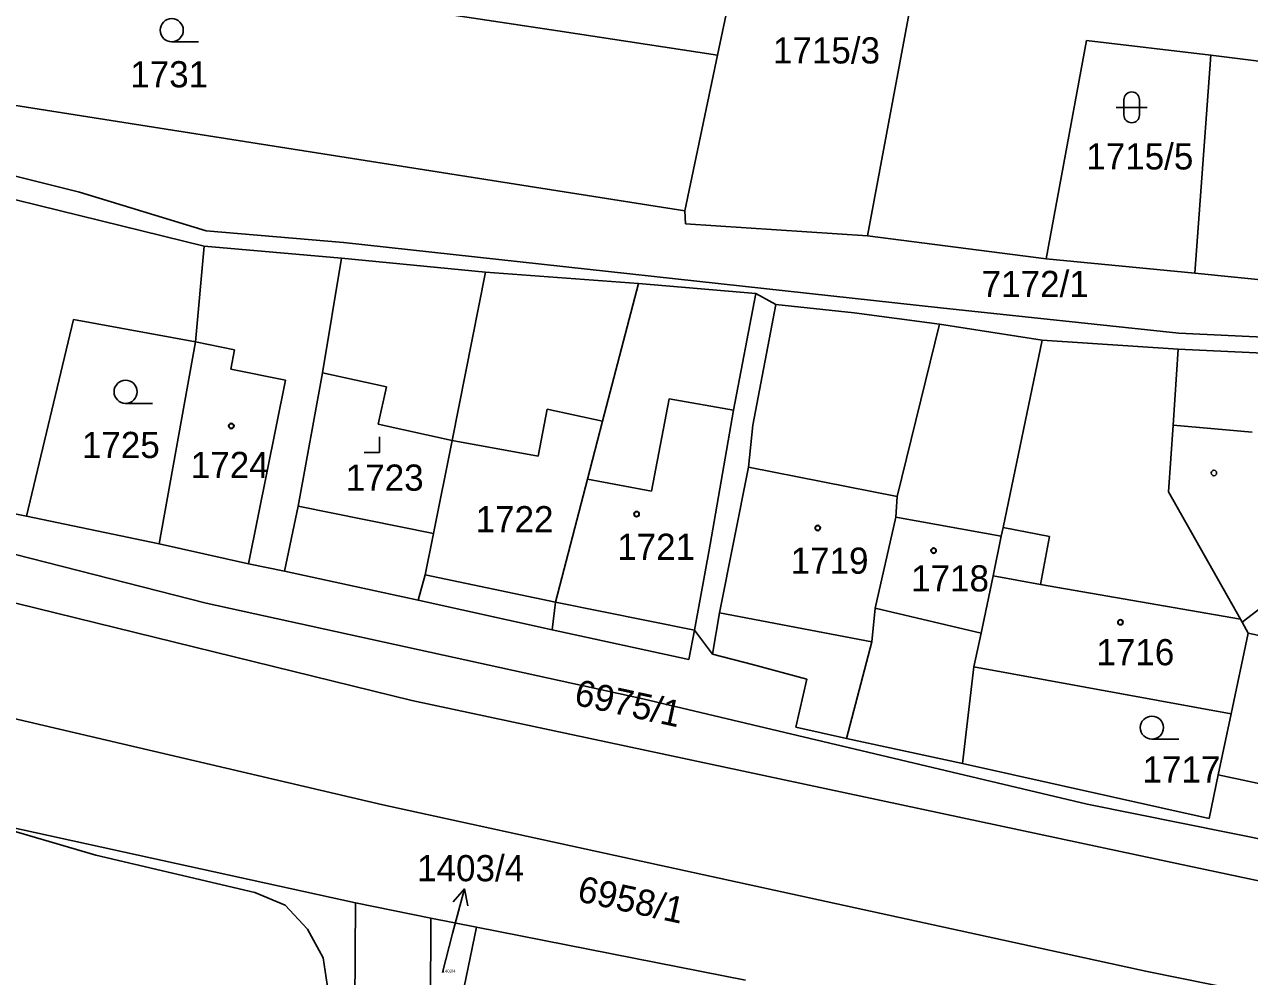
# Model space of a CAD drawing. Extents: x -593183 to -588034, y -1130415 to -1124994.
# Drawn here: x -590080.2 to -590000.6, y -1129409.1 to -1129347.3 of the extents above; entities that cross this region are included whole.
import ezdxf

# ---------------------------------------------------------------- set-up
doc = ezdxf.new("R2010")
doc.units = 0
for name, color, linetype in [('Vrstva 1', 7, 'Continuous'), ('Vrstva 16', 7, 'Continuous'), ('Vrstva 18', 7, 'Continuous'), ('Vrstva 19', 7, 'Continuous'), ('Vrstva 25', 7, 'Continuous'), ('Vrstva 27', 7, 'Continuous'), ('Vrstva 4', 7, 'Continuous')]:
    doc.layers.add(name, color=color, linetype=linetype)

msp = doc.modelspace()

# ---------------------------------------------------------------- linework, layer by layer
at = {"layer": 'Vrstva 1'}
for p, q in [((-590031.96, -1129333.97), (-590035.17, -1129349.33)), ((-590020.91, -1129336.92), (-590025.43, -1129361.05)), ((-590061.71, -1129345.31), (-590045.53, -1129347.76)), ((-590045.53, -1129347.76), (-590035.17, -1129349.33)), ((-590013.83, -1129362.55), (-590011.22, -1129348.37)), ((-590011.22, -1129348.37), (-590003.15, -1129349.34)), ((-590035.17, -1129349.33), (-590037.28, -1129359.43)), ((-590003.15, -1129349.34), (-590004.19, -1129363.49)), ((-590003.15, -1129349.34), (-589985.14, -1129351.52)), ((-590037.28, -1129359.43), (-590088.17, -1129351.42)), ((-590076.58, -1129358.22), (-590088.73, -1129355.19)), ((-590068.5, -1129361.72), (-590085.47, -1129357.56)), ((-590068.36, -1129360.73), (-590076.58, -1129358.22)), ((-590037.24, -1129360.27), (-590037.28, -1129359.43)), ((-590059.44, -1129361.5), (-590068.36, -1129360.73)), ((-590025.43, -1129361.05), (-590037.24, -1129360.27)), ((-590025.43, -1129361.05), (-590013.83, -1129362.55)), ((-590068.5, -1129361.72), (-590069.05, -1129367.94)), ((-590059.58, -1129362.5), (-590068.5, -1129361.72)), ((-590020.69, -1129365.72), (-590059.44, -1129361.5)), ((-590059.58, -1129362.5), (-590060.8, -1129369.94)), ((-590059.58, -1129362.5), (-590050.22, -1129363.41)), ((-590004.19, -1129363.49), (-590013.83, -1129362.55)), ((-590050.22, -1129363.41), (-590052.4, -1129374.34)), ((-590040.3, -1129364.15), (-590050.22, -1129363.41)), ((-590040.3, -1129364.15), (-590042.63, -1129373.08)), ((-590032.69, -1129364.81), (-590040.3, -1129364.15)), ((-589984.38, -1129365.43), (-590004.19, -1129363.49)), ((-590034.14, -1129372.37), (-590032.69, -1129364.81)), ((-590031.38, -1129365.51), (-590032.69, -1129364.81)), ((-590031.38, -1129365.51), (-590032.88, -1129373.34)), ((-590026.3, -1129366.06), (-590031.38, -1129365.51)), ((-590005.21, -1129367.38), (-590020.69, -1129365.72)), ((-590076.98, -1129366.49), (-590080.02, -1129379.26)), ((-590069.05, -1129367.94), (-590076.98, -1129366.49)), ((-590020.76, -1129366.78), (-590026.3, -1129366.06)), ((-590023.51, -1129377.98), (-590020.76, -1129366.78)), ((-590014.1, -1129367.82), (-590020.76, -1129366.78)), ((-589984.93, -1129368.31), (-590005.21, -1129367.38)), ((-590069.05, -1129367.94), (-590071.41, -1129381.05)), ((-590014.1, -1129367.82), (-590016.63, -1129379.99)), ((-590014.1, -1129367.82), (-590005.26, -1129368.41)), ((-590005.59, -1129373.34), (-590005.26, -1129368.41)), ((-589984.99, -1129369.38), (-590005.26, -1129368.41)), ((-590060.8, -1129369.94), (-590062.4, -1129378.61)), ((-590035.65, -1129381.09), (-590034.14, -1129372.37)), ((-590042.63, -1129373.08), (-590043.61, -1129376.86)), ((-590032.88, -1129373.34), (-590033.16, -1129376.07)), ((-590005.88, -1129377.68), (-590005.59, -1129373.34)), ((-590052.4, -1129374.34), (-590053.6, -1129380.37)), ((-590033.16, -1129376.07), (-590035.03, -1129385.52)), ((-590043.61, -1129376.86), (-590045.69, -1129384.83)), ((-590001.22, -1129385.94), (-590005.88, -1129377.68)), ((-590083.99, -1129378.43), (-590080.02, -1129379.26)), ((-590023.6, -1129379.31), (-590023.51, -1129377.98)), ((-590071.41, -1129381.05), (-590080.02, -1129379.26)), ((-590062.4, -1129378.61), (-590063.28, -1129382.83)), ((-590024.94, -1129385.22), (-590023.6, -1129379.31)), ((-590016.63, -1129379.99), (-590016.75, -1129380.55)), ((-590053.6, -1129380.37), (-590054.14, -1129383.07)), ((-590016.75, -1129380.55), (-590017.28, -1129383.12)), ((-590065.62, -1129382.35), (-590071.41, -1129381.05)), ((-590036.66, -1129386.66), (-590035.65, -1129381.09)), ((-590063.28, -1129382.83), (-590065.62, -1129382.35)), ((-590063.28, -1129382.83), (-590054.59, -1129384.7)), ((-590054.14, -1129383.07), (-590054.59, -1129384.7)), ((-590017.28, -1129383.12), (-590018.06, -1129386.85)), ((-590082.19, -1129384.53), (-590055.01, -1129391.21)), ((-590054.59, -1129384.7), (-590045.91, -1129386.62)), ((-590045.69, -1129384.83), (-590045.91, -1129386.62)), ((-590035.03, -1129385.52), (-590035.49, -1129388.2)), ((-590025.14, -1129387.41), (-590024.94, -1129385.22)), ((-590001.1, -1129386.14), (-590001.22, -1129385.94)), ((-590000.71, -1129386.84), (-590001.1, -1129386.14)), ((-590045.91, -1129386.62), (-590037.02, -1129388.56)), ((-590037.02, -1129388.56), (-590036.66, -1129386.66)), ((-590018.06, -1129386.85), (-590018.52, -1129389.04)), ((-590001.83, -1129392.09), (-590000.71, -1129386.84)), ((-590026.79, -1129393.69), (-590025.14, -1129387.41)), ((-590035.49, -1129388.2), (-590032.89, -1129388.87)), ((-590032.89, -1129388.87), (-590029.37, -1129389.83)), ((-590018.52, -1129389.04), (-590019.27, -1129395.3)), ((-590001.83, -1129392.09), (-590018.52, -1129389.04)), ((-590029.37, -1129389.83), (-590030.09, -1129392.94)), ((-590055.01, -1129391.21), (-590005.34, -1129401.8)), ((-590056.9, -1129397.99), (-590084.16, -1129391.61)), ((-590001.83, -1129392.09), (-590002.67, -1129396.05)), ((-590030.09, -1129392.94), (-590026.79, -1129393.69)), ((-590026.79, -1129393.69), (-590019.27, -1129395.3)), ((-590019.27, -1129395.3), (-590003.25, -1129398.87)), ((-590003.25, -1129398.87), (-590002.67, -1129396.05)), ((-590002.67, -1129396.05), (-589989.87, -1129398.75)), ((-590007.28, -1129408.8), (-590056.9, -1129397.99)), ((-590083.72, -1129398.85), (-590075.53, -1129401.25)), ((-590083.72, -1129398.85), (-590058.67, -1129404.34)), ((-590075.53, -1129401.25), (-590065.21, -1129403.68)), ((-590005.34, -1129401.8), (-589982.54, -1129406.63)), ((-590065.21, -1129403.68), (-590063.24, -1129404.51)), ((-590063.24, -1129404.51), (-590061.79, -1129406.07)), ((-590058.67, -1129404.34), (-590058.86, -1129434.44)), ((-590053.86, -1129420.04), (-590053.77, -1129405.34)), ((-590053.77, -1129405.34), (-590050.81, -1129405.93)), ((-590061.79, -1129406.07), (-590060.76, -1129407.93)), ((-590050.81, -1129405.93), (-590033.34, -1129409.38)), ((-590060.76, -1129407.93), (-590060.45, -1129410.08)), ((-589983.97, -1129413.54), (-590007.28, -1129408.8))]:
    msp.add_line(p, q, dxfattribs=at)
msp.add_lwpolyline([(-590035.82, -1129421.91), (-590053.36, -1129418.29), (-590050.81, -1129405.93)], dxfattribs=at)
at = {"layer": 'Vrstva 16'}
msp.add_line((-590053.02, -1129408.88), (-590052.36, -1129406.35), dxfattribs=at)
at = {"layer": 'Vrstva 25'}
for p, q in [((-590068.85, -1129348.46), (-590070.6, -1129348.46)), ((-590008.78, -1129353.22), (-590008.78, -1129352.22)), ((-590007.78, -1129352.22), (-590007.78, -1129353.22)), ((-590009.28, -1129352.72), (-590007.28, -1129352.72)), ((-590071.84, -1129371.93), (-590073.59, -1129371.93)), ((-590057.1, -1129375.11), (-590057.1, -1129374.11)), ((-590057.1, -1129375.11), (-590058.1, -1129375.11)), ((-590005.22, -1129393.73), (-590006.97, -1129393.73)), ((-590052.36, -1129406.35), (-590051.598, -1129403.448))]:
    msp.add_line(p, q, dxfattribs=at)
msp.add_lwpolyline([(-590052.336, -1129404.289), (-590051.598, -1129403.448), (-590051.368, -1129404.543)], dxfattribs=at)
for centre, radius in [((-590070.6, -1129347.71), 0.75), ((-590073.59, -1129371.18), 0.75), ((-590066.73, -1129373.4), 0.175), ((-590066.73, -1129373.4), 0.15), ((-590002.94, -1129376.45), 0.175), ((-590040.42, -1129379.12), 0.175), ((-590040.42, -1129379.12), 0.15), ((-590028.66, -1129380.02), 0.175), ((-590028.66, -1129380.02), 0.15), ((-590021.14, -1129381.49), 0.175), ((-590021.14, -1129381.49), 0.15), ((-590009.01, -1129386.14), 0.175), ((-590009.01, -1129386.14), 0.15), ((-590006.97, -1129392.98), 0.75)]:
    msp.add_circle(centre, radius, dxfattribs=at)
for centre, start, end in [((-590008.28, -1129352.22), 90, 180), ((-590008.28, -1129352.22), 0, 90), ((-590008.28, -1129353.22), 180, 270), ((-590008.28, -1129353.22), 270, 0)]:
    msp.add_arc(centre, 0.5, start, end, dxfattribs=at)
at = {"layer": 'Vrstva 27'}
for p, q in [((-590081.86, -1129381.46), (-590068.36, -1129384.9)), ((-590055.01, -1129391.21), (-590082.19, -1129384.53)), ((-590068.36, -1129384.9), (-590040.01, -1129391.1)), ((-590005.34, -1129401.8), (-590055.01, -1129391.21)), ((-590040.01, -1129391.1), (-590011.16, -1129397.94)), ((-590011.16, -1129397.94), (-589991.31, -1129401.96)), ((-589982.54, -1129406.63), (-590005.34, -1129401.8))]:
    msp.add_line(p, q, dxfattribs=at)
at = {"layer": 'Vrstva 4'}
for p, q in [((-590066.52, -1129368.45), (-590069.05, -1129367.94)), ((-590066.77, -1129369.71), (-590066.52, -1129368.45)), ((-590063.21, -1129370.43), (-590066.77, -1129369.71)), ((-590065.62, -1129382.35), (-590063.21, -1129370.43)), ((-590060.8, -1129369.94), (-590056.65, -1129370.86)), ((-590056.65, -1129370.86), (-590057.19, -1129373.28)), ((-590038.31, -1129371.64), (-590039.45, -1129377.62)), ((-590038.31, -1129371.64), (-590034.14, -1129372.37)), ((-590046.8, -1129375.36), (-590046.23, -1129372.31)), ((-590046.23, -1129372.31), (-590042.63, -1129373.08)), ((-590057.19, -1129373.28), (-590052.4, -1129374.34)), ((-590000.46, -1129373.8), (-590005.59, -1129373.34)), ((-590052.4, -1129374.34), (-590046.8, -1129375.36)), ((-590033.16, -1129376.07), (-590023.51, -1129377.98)), ((-590039.45, -1129377.62), (-590043.61, -1129376.86)), ((-590062.4, -1129378.61), (-590053.6, -1129380.37)), ((-590023.6, -1129379.31), (-590016.75, -1129380.55)), ((-590016.63, -1129379.99), (-590013.62, -1129380.58)), ((-590013.62, -1129380.58), (-590014.2, -1129383.69)), ((-590054.14, -1129383.07), (-590045.69, -1129384.83)), ((-590014.2, -1129383.69), (-590017.28, -1129383.12)), ((-590014.2, -1129383.69), (-590001.22, -1129385.94)), ((-590045.69, -1129384.83), (-590036.66, -1129386.66)), ((-590035.03, -1129385.52), (-590025.14, -1129387.41)), ((-590018.06, -1129386.85), (-590024.94, -1129385.22)), ((-590001.1, -1129386.14), (-589999.8, -1129385.14)), ((-590036.66, -1129386.66), (-590035.49, -1129388.2)), ((-589991.8, -1129388.84), (-590000.71, -1129386.84)), ((-590058.67, -1129404.34), (-590053.77, -1129405.34))]:
    msp.add_line(p, q, dxfattribs=at)

# ---------------------------------------------------------------- texts
at = {"layer": 'Vrstva 16'}
msp.add_text('1403/4', height=1.7, dxfattribs=at).set_placement((-590054.67, -1129402.95))
at = {"layer": 'Vrstva 18'}
for s, height, p in [('1715/3', 1.7, (-590031.57, -1129349.87)), ('1731', 1.7, (-590073.29, -1129351.42)), ('1715/5', 1.7, (-590011.231, -1129356.75)), ('7172/1', 1.7, (-590018.02, -1129365.03)), ('1725', 1.7, (-590076.43, -1129375.48)), ('1722', 1.7, (-590050.87, -1129380.3)), ('1717', 1.7, (-590007.58, -1129396.54)), ('1403/4', 0.2, (-590053.02, -1129408.88))]:
    msp.add_text(s, height=height, dxfattribs=at).set_placement(p)
for s, p in [('6975/1', (-590044.54, -1129391.48)), ('6958/1', (-590044.34, -1129404.23))]:
    msp.add_text(s, height=1.7, rotation=347.70474, dxfattribs=at).set_placement(p)
at = {"layer": 'Vrstva 19'}
for s, p in [('1724', (-590069.36, -1129376.78)), ('1723', (-590059.3, -1129377.6)), ('1721', (-590041.68, -1129382.09)), ('1719', (-590030.42, -1129382.99)), ('1718', (-590022.6, -1129384.14)), ('1716', (-590010.57, -1129388.93))]:
    msp.add_text(s, height=1.7, dxfattribs=at).set_placement(p)

doc.saveas('drawing.dxf')
